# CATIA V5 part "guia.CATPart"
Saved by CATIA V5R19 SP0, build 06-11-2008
Part number: guia
Bounding box of the stored display mesh (mm): x -5486.766 to 0, y -1000.9 to 1000.9, z 0 to 13295.846
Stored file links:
  E:\Luis\Dropbox\3DIT\Parking\planos\cat 3 dit park8\guia.CATPart
  E:\Luis\Dropbox\3DIT\Parking\planos\cat 3 dit park8\ensamble eslabon.CATProduct
  E:\Luis\Dropbox\3DIT\Parking\planos\cat 3 dit park8\ensamble Parking3d.CATProduct
  E:\Luis\Dropbox\3DIT\Parking\planos\cat 3 dit park8\eslabon.CATPart
  E:\Luis\Dropbox\3DIT\Parking\planos\cat 3 dit park8\ensamble unico eslabon.CATProduct
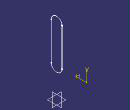
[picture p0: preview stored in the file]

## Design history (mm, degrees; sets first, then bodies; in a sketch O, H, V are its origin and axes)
External parameters (linked from other documents)
  External.P = 625
  External.b1 = 38.1
  External.b2 = 50.8
  External.d1 = 50.8
  External.d2 = 26.4
  External.i1 = 101.6
  External.i2 = 154.4
  External.g = 50.8
  External.LE = 800
  External.Z1 = 10
  External.Z2 = 10
  External.GL = 6150
Body1 (main body)
  DatumSurface1
  DatumCurve1 to DatumCurve3
  Plane1: stored without definition
  DatumCurve4
  DatumPoint1
  Sketch1 on Plane1, origin (-5486.7658, 0, 0), H (0, -1, 0), V (0, 0, 1)
    line L1 (3963.8373, 8374.3504) -> (3963.8373, 6424.3504)
    line L2 (3963.8373, 6424.3504) -> (1263.8373, 6424.3504)
    line L3 (1263.8373, 6424.3504) -> (1263.8373, 8374.3504)
    line L4 (1263.8373, 8374.3504) -> (3963.8373, 8374.3504)
    point P5 (2613.8373, 8263.3504)
    construction arc A1 centre (-520, 3300) radius 1300 from (-1820, 3300) to (-520, 2000) ccw
    point P6 (-1820, 3300)
    point P7 (-520, 2000)
    construction line L5 (-520, 2000) -> (520, 2000)
    point P8 (-520, 2000)
    point P9 (520, 2000)
    construction arc A2 centre (520, 3300) radius 1300 from (520, 2000) to (1820, 3300) ccw
    point P10 (520, 2000)
    point P11 (1820, 3300)
    construction line L6 (1820, 3300) -> (1820, 8940)
    point P12 (1820, 3300)
    point P13 (1820, 8940)
    construction arc A3 centre (520, 8940) radius 1300 from (1820, 8940) to (520, 10240) ccw
    point P14 (1820, 8940)
    point P15 (520, 10240)
    construction line L7 (-520, 10240) -> (520, 10240)
    point P16 (-520, 10240)
    point P17 (520, 10240)
    construction arc A4 centre (-520, 8940) radius 1300 from (-520, 10240) to (-1820, 8940) ccw
    point P18 (-520, 10240)
    point P19 (-1820, 8940)
    construction line L8 (-1820, 3300) -> (-1820, 8940)
    point P20 (-1820, 3300)
    point P21 (-1820, 8940)
    construction line L9 (0, 8940) -> (0, 3300)
    point P22 (0, 8940)
    construction line L10 (1300, 8940) -> (1300, 3300)
    construction line L11 (-1300, 3300) -> (-1300, 8940)
    construction arc A5 centre (0, 3300) radius 1300 from (1300, 3300) to (-1300, 3300) cw
    construction arc A6 centre (0, 8940) radius 1300 from (-1300, 8940) to (1300, 8940) cw
    construction line L12 (0, 8940) -> (0, 3300)
    line L13 (2700, 8940) -> (2700, 3300)
    line L14 (-2700, 3300) -> (-2700, 8940)
    arc A7 centre (0, 3300) radius 2700 from (2700, 3300) to (-2700, 3300) cw
    arc A8 centre (0, 8940) radius 2700 from (-2700, 8940) to (2700, 8940) cw
    line L15 (1350, 5175.5107) -> (4050, 5175.5107)
    line L16 (1350, 3225.5107) -> (1350, 5175.5107)
    line L17 (4050, 3225.5107) -> (1350, 3225.5107)
    line L18 (4050, 5175.5107) -> (4050, 3225.5107)
    point P32 (2700, 5064.5107)
    reference projected line E1 (-977.5, 10340) -> (962.5, 10340) from edge of DatumCurve4
    reference projected point E2 (1740, 0) from vertex of DatumPoint1
    distance L2 L4 = 1950
    length L4 = 2700
    distance P5 L4 = 111
    distance P5 L1 = 1350
    distance L12 L13 = 2700
    distance L17 L15 = 1950
    length L15 = 2700
    distance P32 L15 = 111
    distance P32 L18 = 1350
    distance P32 P5 = 3200
    distance E1 E2 = 10340 (reference)
    horizontal: L4 H, L2 H, L15 H, L17 H
    vertical: L3 V, L1 V, L9 V, L12 V, L16 V, L18 V
    fix: A1, P6, P7, L5, P8, P9, A2, P10, P11, L6, P12, P13, A3, P14, P15, L7, P16, P17, A4, P18, P19, L8, P20, P21, A8
    coincidence: P22 V, P5 A8, P32 L13
    tangency: A5 L10, A6 L10, A5 L11, A6 L11, A7 L13, A8 L13, A7 L14, A8 L14
  DatumPoint2 to DatumPoint4
  DatumCurve5 to DatumCurve7
  Sketch2, origin (313.2342, 7.5, 8738.041), H (0, 1, 0), V (0, 0, 1), geometry linked from another document
  Sketch3 on yz-plane, origin (0, 0, 0), H (0, 1, 0), V (0, 0, 1)
    construction line L1 (-1820, 8975) -> (1820, 8975)
    construction line L2 (1820, 8975) -> (1820, 4325)
    construction line L3 (1820, 4325) -> (-1820, 4325)
    construction line L4 (-1820, 4325) -> (-1820, 8975)
    point P7 (0, 11088.4858)
    construction circle A1 centre (0, 9480) radius 1820
    point P8 (0, 9480)
    construction line L5 (0, 8975) -> (0, 9480)
    point P9 (0, 8975)
    point P10 (0, 9480)
    reference projected point E6 (0, 11300) from Sketch2
    construction line L6 (-1820, 3820) -> (1820, 3820)
    point P11 (-1820, 3820)
    point P12 (1820, 3820)
    construction line L7 (0, 3820) -> (0, 4325)
    point P13 (0, 3820)
    point P14 (0, 4325)
    construction circle A2 centre (0, 3820) radius 1820
    construction line L8 (1820, 9480) -> (1820, 3820)
    point P15 (1820, 9480)
    point P16 (1820, 3820)
    line L9 (1820, 9480) -> (1820, 3820)
    point P17 (1820, 9480)
    point P18 (1820, 3820)
    line L10 (-1820, 9480) -> (-1820, 3820)
    point P19 (-1820, 9480)
    point P20 (-1820, 3820)
    arc A3 centre (0, 9480) radius 1820 from (1820, 9480) to (-1820, 9480) ccw
    point P22 (0, 11300)
    arc A4 centre (0, 3820) radius 1820 from (1820, 3820) to (-1820, 3820) cw
    point P24 (0, 2000)
    construction line L11 (0, 8975) -> (-3100, 8975)
    construction line L12 (-3100, 8975) -> (-3100, 3820)
    construction line L13 (-3100, 3820) -> (0, 3820)
    construction line L14 (0, 3820) -> (0, 8975)
    point P27 (0, 3820)
    radius A1 = 1820 (reference)
    length L5 = 505 (reference)
    distance L6 L1 = 5155
    radius A2 = 1820 (reference)
    length L11 = 3100
    horizontal: L1 H, L3 H, L6 H, L11 H, L13 H
    vertical: L2 V, L4 V, L5 V, L7 V, L12 V, L14 V
    coincidence: P7 V, P10 P8, E6 A1, L2 P12, P11 L4, A1 P15, A2 P16, A1 P17, A2 P18, A1 P19, A2 P20, A3 P22, P22 L7, P22 A1, A4 P24, P24 L7, P24 A2, P13 P27
    midpoint: P9 L1, P13 L6, P14 L3
    tangency: L8 A1, L8 A2, L9 A1, L9 A2, L10 A1, L10 A2, A3 L4, A4 L4
  Line1 to Line3: stored without definition
  Sketch4 on yz-plane, origin (0, 0, 475.1432), H (0, 1, 0), V (0, 0, 1)
    arc A1 centre (780, 12000) radius 1820 from (2600, 12000) to (780, 13820) ccw
    point P1 (780, 12000)
    line L1 (780, 13820) -> (780, 13620)
    point P2 (780, 5620)
    arc A2 centre (780, 5620) radius 1820 from (780, 3800) to (2600, 5620) ccw
    line L2 (2600, 12000) -> (2600, 5620)
    point P3 (2600, 12000)
    point P4 (2600, 5620)
    line L3 (2400, 12000) -> (2400, 5620)
    point P5 (2400, 12000)
    point P6 (2400, 5620)
    arc A3 centre (780, 12000) radius 1620 from (2400, 12000) to (780, 13620) ccw
    arc A4 centre (780, 5620) radius 1620 from (780, 4000) to (2400, 5620) ccw
    point P7 (780, 13820)
    point P8 (780, 3800)
    point P9 (780, 13620)
    point P10 (780, 4000)
    line L4 (780, 4000) -> (780, 3800)
    axis line L5 (0, 11422.2023) -> (0, 869.72)
    point P11 (0, 11422.2023)
    point P15 (-2600, 12000)
    point P16 (-2400, 12000)
    point P17 (-2400, 5620)
    point P18 (-780, 13820)
    point P19 (-780, 3800)
    point P20 (-780, 13620)
    point P21 (-780, 4000)
    arc A5 centre (-780, 12000) radius 1820 from (-2600, 12000) to (-780, 13820) cw
    line L6 (-780, 13820) -> (-780, 13620)
    arc A6 centre (-780, 5620) radius 1820 from (-780, 3800) to (-2600, 5620) cw
    line L7 (-2600, 12000) -> (-2600, 5620)
    line L8 (-2400, 12000) -> (-2400, 5620)
    arc A7 centre (-780, 12000) radius 1620 from (-2400, 12000) to (-780, 13620) cw
    arc A8 centre (-780, 5620) radius 1620 from (-780, 4000) to (-2400, 5620) cw
    line L9 (-780, 4000) -> (-780, 3800)
    point P24 (-780, 13720)
    point P25 (780, 13720)
    construction line L10 (780, 13720) -> (-780, 13720)
    construction line L11 (-200, 12820) -> (200, 12820)
    distance A1 A3 = 200
    distance A4 A2 = 200
    distance P1 P2 = 6380
    distance P10 L2 = 1820
    distance L10 L11 = 900
    distance L3 V = 2400
    distance P16 H = 12000
    vertical: L1 V, L4 V, L5 V
    tangency: L2 A1, L2 A2, A3 L3, A4 L3
    coincidence: A2 P4, P1 L1, P2 L1, L1 P10, L1 L4, P11 V, P4 L2
    concentricity: A1 A3, A2 A4
    symmetry: P3 P15 L5, P5 P16 L5, P6 P17 L5, P7 P18 L5, P8 P19 L5, P9 P20 L5, P10 P21 L5, A1 A5 L5, L1 L6 L5, A2 A6 L5, L2 L7 L5, L3 L8 L5, A3 A7 L5, A4 A8 L5, L4 L9 L5
    midpoint: P24 L6, P25 L1
    horizontal: L10 H
  Pad1: profile Sketch4, direction (1, 0, 0), length 10
  DatumCurve8
  Sketch5 on face of Pad3, origin (10, 0, 0), H (0, 1, 0), V (0, 0, 1)
    arc A1 centre (779.9998, 10355.143) radius 1820.0002 from (2600, 10355.143) to (779.9998, 12175.1432) ccw
    point P1 (2600, 10355.143)
    point P2 (779.9998, 12175.1432)
    line L1 (2600, 10355.143) -> (2600, 4475.1434)
    point P3 (2600, 4475.1434)
    arc A2 centre (779.9998, 4475.1434) radius 1820.0002 from (779.9998, 2655.1432) to (2600, 4475.1434) ccw
    line L2 (779.9998, 2655.1432) -> (779.9998, 2855.1432)
    arc A3 centre (779.9998, 4475.1434) radius 1620.0002 from (779.9998, 2855.1432) to (2400, 4475.1434) ccw
    line L3 (2400, 4475.1434) -> (2400, 10355.143)
    arc A4 centre (779.9998, 10355.143) radius 1620.0002 from (2400, 10355.143) to (779.9998, 11975.1432) ccw
    point P8 (779.9998, 11975.1432)
    line L4 (779.9998, 11975.1432) -> (779.9998, 12175.1432)
    line L5 (-2600, 4475.1434) -> (-2600, 10355.143)
    arc A5 centre (-779.9998, 10355.143) radius 1820.0002 from (-779.9998, 12175.1432) to (-2600, 10355.143) ccw
    point P11 (-779.9998, 12175.1432)
    line L6 (-779.9998, 12175.1432) -> (-779.9998, 11975.1432)
    point P12 (-779.9998, 11975.1432)
    arc A6 centre (-779.9998, 10355.143) radius 1620.0002 from (-779.9998, 11975.1432) to (-2400, 10355.143) ccw
    line L7 (-2400, 10355.143) -> (-2400, 4475.1434)
    arc A7 centre (-779.9998, 4475.1434) radius 1620.0002 from (-2400, 4475.1434) to (-779.9998, 2855.1432) ccw
    line L8 (-779.9998, 2855.1432) -> (-779.9998, 2655.1432)
    arc A8 centre (-779.9998, 4475.1434) radius 1820.0002 from (-2600, 4475.1434) to (-779.9998, 2655.1432) ccw
    reference projected line E1 (2400, 9602.2023) -> (2400, 3722.2023) from edge [face of Pad1 from Sketch4.L3 | end face of Pad1]
    reference projected point E2 (780, 14295.1432) from vertex [face of Pad1 from Sketch4.L1 | face of Pad1 from Sketch4.A1 | end face of Pad1]
    reference projected line E3 (-2400, 6243.23) -> (-2400, 12123.23) from edge [face of Pad1 from Sketch4.L8 | end face of Pad1]
    construction line L9 (-779.9998, 12075.1432) -> (779.9998, 12075.1432)
    point P17 (-779.9998, 12075.1432)
    point P18 (779.9998, 12075.1432)
    construction line L10 (-2400, 4475.1434) -> (2400, 4475.1434)
    radius A1 = 1820.0002
    radius A4 = 1620.0002
    radius A2 = 1820.0002
    radius A5 = 1820.0002
    radius A6 = 1620.0002
    radius A8 = 1820.0002
    distance P8 P2 = 200
    distance P11 P12 = 200
    distance P1 P3 = 5879.9996
    distance E2 P8 = 2320
    distance L7 E3 = 0
    vertical: L8 V, L7 V, L6 V, L5 V, L4 V, L3 V, L2 V, L1 V
    tangency: A1 L1, L1 A2, A3 L3, L3 A4, L5 A5, L5 A8, A6 L7, L7 A7
    concentricity: A1 A4, A2 A3, A5 A6, A7 A8
    coincidence: L2 L4, L6 L8, L3 E1
    midpoint: P17 L6, P18 L4
    horizontal: L9 H, L10 H
  Pad2: profile Sketch5, direction (1, 0, 0), up to start face of Pad1
  Sketch6 on end face of Pad1, origin (10, 0, 0), H (0, 1, 0), V (0, 0, 1)
  Pad3: profile Sketch6, direction (-1, 0, 0), length 70, thin wall 5
  Sketch7 on face of Pad3, origin (0, 785, 0), H (-1, 0, 0), V (0, 0, 1)
  Pocket1: profile Sketch7, direction (0, -1, 0), up to face of Pad3
  DatumPoint5
  Sketch8 on yz-plane, origin (0, 0, 0), H (0, 1, 0), V (0, 0, 1)
    construction line L1 (-780, 4475.1432) -> (-780, 4275.1432)
    construction line L2 (780, 4475.1432) -> (780, 4275.1432)
    construction line L3 (780, 4375.1432) -> (-780, 4375.1432)
    point P1 (780, 4375.1432)
    point P2 (-780, 4375.1432)
    reference projected line E5 (-780, 14295.1432) -> (-780, 14095.1432) from edge [face of Pad3 | face of Pad3]
    reference projected line E6 (780, 14095.1432) -> (780, 14295.1432) from edge [face of Pad3 | face of Pad3]
    construction line L4 (-780, 14195.1432) -> (780, 14195.1432)
    point P7 (-780, 14195.1432)
    point P8 (780, 14195.1432)
    construction line L5 (0, 14195.1432) -> (0, 12295.1432)
    point P9 (0, 14195.1432)
    construction line L6 (0, 12295.1432) -> (0, 5375.1432)
    line L7 (1000, 12295.1432) -> (1000, 5375.1432)
    line L8 (-1000, 5375.1432) -> (-1000, 12295.1432)
    arc A1 centre (0, 5375.1432) radius 1000 from (1000, 5375.1432) to (-1000, 5375.1432) cw
    arc A2 centre (0, 12295.1432) radius 1000 from (-1000, 12295.1432) to (1000, 12295.1432) cw
    length L5 = 1900 (reference)
    distance L6 L7 = 1000
    length L6 = 6920 (reference)
    length L6 = 6920
    vertical: L1 V, L2 V, L5 V, L6 V
    midpoint: P1 L2, P2 L1, P7 E5, P8 E6, P9 L4
    horizontal: L3 H, L4 H
    tangency: A1 L7, A2 L7, A1 L8, A2 L8, A1 L3
  DatumCurve9
  DatumCurve10
  Plane2: type 2Lines, Element1 DatumCurve9, Element2 DatumCurve10
  Sketch9 on yz-plane, origin (0, 0, 0), H (0, -1, 0), V (0, 0, 1)
    point P1 (975.5, 12295.1432)
    point P2 (975.5, 5375.1432)
    point P3 (975.5, 12295.1432)
    point P4 (-975.5, 12295.1432)
    point P5 (-975.5, 5375.1432)
    point P6 (-975.5, 12295.1432)
    point P7 (-975.5, 5375.1432)
    point P8 (975.5, 5375.1432)
    line L1 (975.5, 12295.1432) -> (975.5, 5375.1432)
    line L2 (-975.5, 5375.1432) -> (-975.5, 12295.1432)
    arc A1 centre (0, 5375.1432) radius 975.5 from (-975.5, 5375.1432) to (975.5, 5375.1432) ccw
    arc A2 centre (0, 12295.1432) radius 975.5 from (975.5, 12295.1432) to (-975.5, 12295.1432) ccw
    reference projected arc E1 centre (0, 12295.1432) radius 1000 from (1000, 12295.1432) to (-1000, 12295.1432) ccw from Sketch8.A2
    reference projected line E2 (1000, 11255.1432) -> (1000, 5375.1432) from Sketch8.L8
    reference projected arc E3 centre (0, 5375.1432) radius 1000 from (-1000, 5375.1432) to (1000, 5375.1432) ccw from Sketch8.A1
    reference projected line E4 (-1000, 5375.1432) -> (-1000, 11255.1432) from Sketch8.L7
    reference projected arc E5 centre (0, 12295.1432) radius 1000 from (1000, 12295.1432) to (-1000, 12295.1432) ccw from Sketch8.A2
    distance P1 P2 = 6920 (reference)
    distance A2 E5 = 24.5
    coincidence: P3 P1, A2 P1, P6 P4, L2 P4, P7 P5, A1 P5, P2 P8
    tangency: A2 L1, L2 A2, A1 L1, L2 A1
    vertical: E4 V, E2 V, L2 V, L1 V
    concentricity: A1 E3, A2 E1
  Extract1: ExtractElem Sketch9.A1
  CurvePar1: Offset1 25.4, Offset2 0, Offset Extract1
Relations
  Sketch8.length(L6) = deleted_Real /1000 (deactivated)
